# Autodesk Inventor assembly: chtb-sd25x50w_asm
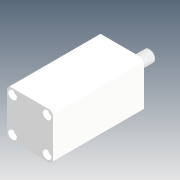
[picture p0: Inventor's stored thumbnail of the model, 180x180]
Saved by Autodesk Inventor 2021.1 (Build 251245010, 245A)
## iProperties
Company: Microsoft
Created: 2018-05
Part Number: chtb-sd25x50w_asm
Description: STEP AP214
Document SubType Name: Assembly
Designer: user
Title: chtb-sd25x50w_asm.STEP
Author: Windows
Revision Number: ÈÎºÎ
Sending System: SolidWorks 2015
Preprocessor: SwSTEP 2.0
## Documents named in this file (4)
- D:\Vault_2016\Projekty\Clamptek\Hydraulic\CHTB\CHTB-25\Inventor\chtb-sd25x50w\chtb-sd25x50w_asm.iam
- D:\Vault_2016\Projekty\Clamptek\Hydraulic\CHTB\CHTB-25\Inventor\chtb-sd25x50w\CHTB-25QG.ipt
- D:\Vault_2016\Projekty\Clamptek\Hydraulic\CHTB\CHTB-25\Inventor\chtb-sd25x50w\CHTB-SD25X50NBT.ipt
- D:\Vault_2016\Projekty\Clamptek\Hydraulic\CHTB\CHTB-25\Inventor\chtb-sd25x50w\CHTB-SD25X50WHSG.ipt
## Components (3 placed, 3 different names)
1. CHTB-25QG_1
2. CHTB-SD25X50NBT_2
3. CHTB-SD25X50WHSG_3
